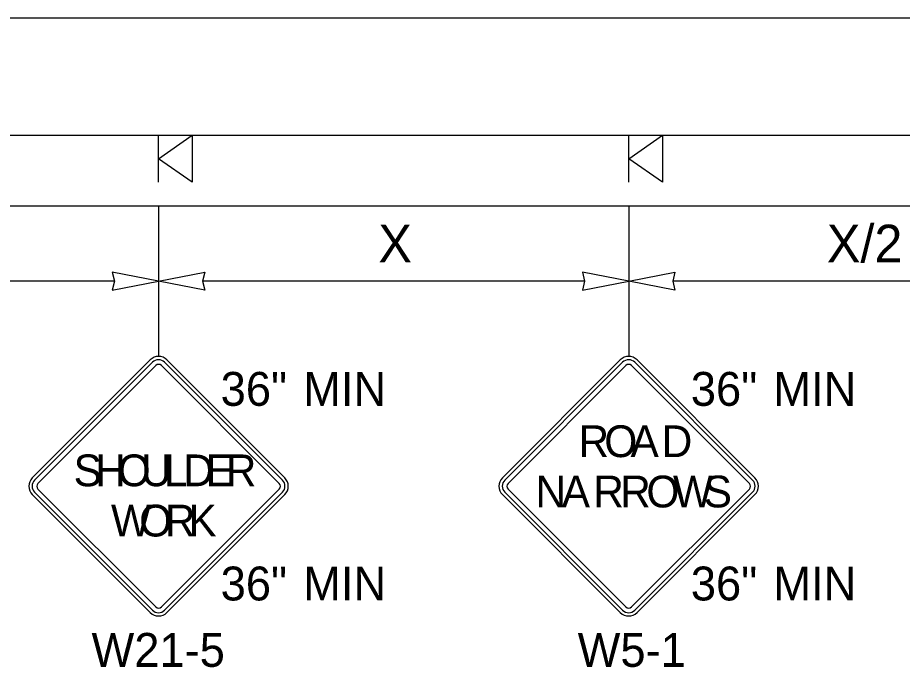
# Model space of a CAD drawing. Extents: x 99999.1 to 100096.1, y 99995 to 100010.7.
# Drawn here: x 100022.749 to 100024.63, y 100004.005 to 100005.386 of the extents above; entities that cross this region are included whole.
import ezdxf

# ---------------------------------------------------------------- set-up
doc = ezdxf.new("R2010")
doc.units = 0
for name, color, linetype in [('RD_ED_ShoulderPavedEdge', 7, 'Continuous'), ('RD_MK_LineEdgeWhite', 7, 'Continuous'), ('TR_SN_ConstructionSigns', 7, 'Continuous'), ('TR_WZ_PortableSignMountBlk-Org', 7, 'Continuous'), ('TR_WZ_WorkZoneDetails', 7, 'Continuous'), ('TR_WZ_WorkZoneTextCurrent', 7, 'Continuous')]:
    doc.layers.add(name, color=color, linetype=linetype)

msp = doc.modelspace()

# ---------------------------------------------------------------- linework, layer by layer
at = {"layer": 'RD_ED_ShoulderPavedEdge'}
msp.add_line((100020.8283, 100004.9857), (100034.8933, 100004.9857), dxfattribs=at)
at = {"layer": 'RD_MK_LineEdgeWhite'}
msp.add_line((100020.8283, 100005.3857), (100034.8933, 100005.3857), dxfattribs=at)
at = {"layer": 'TR_SN_ConstructionSigns'}
for p, q in [((100023.0307, 100004.6583), (100022.7801, 100004.4077)), ((100023.0357, 100004.6533), (100022.7851, 100004.4028)), ((100022.7921, 100004.3958), (100023.0426, 100004.6464)), ((100023.0546, 100004.6464), (100023.3052, 100004.3958)), ((100023.3121, 100004.4028), (100023.0615, 100004.6533)), ((100023.3171, 100004.4077), (100023.0665, 100004.6583)), ((100024.0307, 100004.6583), (100023.7801, 100004.4077)), ((100024.0357, 100004.6533), (100023.7851, 100004.4028)), ((100023.7921, 100004.3958), (100024.0426, 100004.6464)), ((100024.0546, 100004.6464), (100024.3052, 100004.3958)), ((100024.3121, 100004.4028), (100024.0615, 100004.6533)), ((100024.3171, 100004.4077), (100024.0665, 100004.6583)), ((100023.0426, 100004.1333), (100022.7921, 100004.3839)), ((100023.3052, 100004.3839), (100023.0546, 100004.1333)), ((100024.0426, 100004.1333), (100023.7921, 100004.3839)), ((100024.3052, 100004.3839), (100024.0546, 100004.1333)), ((100022.7801, 100004.3719), (100023.0307, 100004.1214)), ((100022.7851, 100004.3769), (100023.0357, 100004.1263)), ((100023.0615, 100004.1263), (100023.3121, 100004.3769)), ((100023.0665, 100004.1214), (100023.3171, 100004.3719)), ((100023.7801, 100004.3719), (100024.0307, 100004.1214)), ((100023.7851, 100004.3769), (100024.0357, 100004.1263)), ((100024.0615, 100004.1263), (100024.3121, 100004.3769)), ((100024.0665, 100004.1214), (100024.3171, 100004.3719))]:
    msp.add_line(p, q, dxfattribs=at)
for centre, radius, start, end in [((100023.0486, 100004.6404), 0.0253, 45, 135), ((100024.0486, 100004.6404), 0.0253, 45, 135), ((100023.0486, 100004.6404), 0.0183, 45, 135), ((100023.0486, 100004.6404), 0.00844, 45, 135), ((100024.0486, 100004.6404), 0.0183, 45, 135), ((100024.0486, 100004.6404), 0.00844, 45, 135), ((100022.798, 100004.3898), 0.0253, 135, 225), ((100022.798, 100004.3898), 0.0183, 135, 225), ((100023.2992, 100004.3898), 0.0183, 315, 45), ((100023.2992, 100004.3898), 0.0253, 315, 45), ((100023.798, 100004.3898), 0.0253, 135, 225), ((100023.798, 100004.3898), 0.0183, 135, 225), ((100024.2992, 100004.3898), 0.0183, 315, 45), ((100024.2992, 100004.3898), 0.0253, 315, 45), ((100022.798, 100004.3898), 0.00844, 135, 225), ((100023.2992, 100004.3898), 0.00844, 315, 45), ((100023.798, 100004.3898), 0.00844, 135, 225), ((100024.2992, 100004.3898), 0.00844, 315, 45), ((100023.0486, 100004.1393), 0.0253, 225, 315), ((100023.0486, 100004.1393), 0.0183, 225, 315), ((100023.0486, 100004.1393), 0.00844, 225, 315), ((100024.0486, 100004.1393), 0.0253, 225, 315), ((100024.0486, 100004.1393), 0.0183, 225, 315), ((100024.0486, 100004.1393), 0.00844, 225, 315)]:
    msp.add_arc(centre, radius, start, end, dxfattribs=at)
at = {"layer": 'TR_WZ_PortableSignMountBlk-Org'}
for p, q in [((100023.0486, 100005.0358), (100023.0486, 100005.1358)), ((100024.0486, 100005.0358), (100024.0486, 100005.1358))]:
    msp.add_line(p, q, dxfattribs=at)
for points in [[(100023.0486, 100005.0857), (100023.1204, 100005.1358), (100023.1204, 100005.0358)], [(100024.0486, 100005.0857), (100024.1204, 100005.1358), (100024.1204, 100005.0358)]]:
    msp.add_lwpolyline(points, close=True, dxfattribs=at)
at = {"layer": 'TR_WZ_WorkZoneDetails'}
for p, q in [((100021.4486, 100005.1358), (100025.9101, 100005.1358)), ((100023.0486, 100004.986), (100023.0486, 100004.6657)), ((100024.0486, 100004.986), (100024.0486, 100004.6657)), ((100022.9549, 100004.8257), (100022.3423, 100004.8257)), ((100023.9549, 100004.8257), (100023.1423, 100004.8257)), ((100024.9549, 100004.8257), (100024.1423, 100004.8257))]:
    msp.add_line(p, q, dxfattribs=at)
for points in [[(100023.0486, 100004.8257), (100022.9503, 100004.845), (100022.9549, 100004.8257), (100022.9503, 100004.8065)], [(100023.0486, 100004.8257), (100023.1469, 100004.845), (100023.1423, 100004.8257), (100023.1469, 100004.8065)], [(100024.0486, 100004.8257), (100023.9503, 100004.845), (100023.9549, 100004.8257), (100023.9503, 100004.8065)], [(100024.0486, 100004.8257), (100024.1469, 100004.845), (100024.1423, 100004.8257), (100024.1469, 100004.8065)]]:
    msp.add_lwpolyline(points, close=True, dxfattribs=at)

# ---------------------------------------------------------------- texts
at = {"layer": 'TR_SN_ConstructionSigns'}
for s, p in [('36"', (100023.1807, 100004.5607)), ('MIN', (100023.3562, 100004.5607)), ('36"', (100024.1807, 100004.5607)), ('MIN', (100024.3562, 100004.5607)), ('36"', (100023.1807, 100004.147)), ('MIN', (100023.3562, 100004.147)), ('36"', (100024.1807, 100004.147)), ('MIN', (100024.3562, 100004.147)), ('W21-5', (100022.9061, 100004.0059)), ('W5-1', (100023.94, 100004.0059))]:
    msp.add_text(s, height=0.072, rotation=360, dxfattribs=at).set_placement(p)
for s, p in [('R', (100023.9417, 100004.4517)), ('O', (100023.9966, 100004.4517)), ('A', (100024.0524, 100004.4517)), ('D', (100024.1187, 100004.4517)), ('S', (100022.8679, 100004.3898)), ('H', (100022.914, 100004.3898)), ('O', (100022.9616, 100004.3898)), ('U', (100023.0113, 100004.3898)), ('L', (100023.0599, 100004.3898)), ('D', (100023.1012, 100004.3898)), ('E', (100023.1488, 100004.3898)), ('R', (100023.1915, 100004.3898)), ('N', (100023.8503, 100004.3448)), ('A', (100023.9061, 100004.3448)), ('R', (100023.9733, 100004.3448)), ('R', (100024.0304, 100004.3448)), ('O', (100024.0862, 100004.3448)), ('W', (100024.1427, 100004.3448)), ('S', (100024.208, 100004.3448)), ('W', (100022.9474, 100004.283)), ('O', (100023.0074, 100004.283)), ('R', (100023.0619, 100004.283)), ('K', (100023.1121, 100004.283))]:
    msp.add_text(s, height=0.0675, dxfattribs=at).set_placement(p)
at = {"layer": 'TR_WZ_WorkZoneTextCurrent'}
for s, p in [('X', (100023.5161, 100004.8657)), ('X/2', (100024.4701, 100004.8657))]:
    msp.add_text(s, height=0.08, rotation=360, dxfattribs=at).set_placement(p)

doc.saveas('drawing.dxf')
